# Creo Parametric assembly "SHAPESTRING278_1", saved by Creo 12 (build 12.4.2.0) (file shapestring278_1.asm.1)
Units: Custom; MM, KILOGRAM, SECS

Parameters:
  PTC_WM_ITERATION = "0"
  PTC_WM_VERSION = "-.0"
  PTC_WM_LIFECYCLE_STATE = "In Work"
  PTC_WM_LIFECYCLE = "MO_CADDocument"
  PTC_WM_CREATED_BY = "Maximilian Roepper (Z0017RMS: MO)"
  PTC_WM_CREATED_ON = "18-Sep-26 11:36:42 AM"
  PTC_WM_MODIFIED_BY = "Maximilian Roepper (Z0017RMS: MO)"
  PTC_WM_MODIFIED_ON = "18-Sep-26 11:36:46 AM"
  PDMLINKNUMBER = "PDM000071455016"
  PTC_WM_NUMBER = "PDM000071455016"

Other parameters: WEIGHT, WEIGHT_FACTOR, WEIGHT_ADD, MC_ERRORS, SUPPLIER

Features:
  1. coordinate system
  2. imported feature
  3. component "SHAPESTRING065_1"
  4. component "SHAPESTRING275_1"
  5. component "SHAPESTRING276_1"
  6. component "SHAPESTRING277_1"

Other named items: DRW_VIEW_ORG, ROUGH-GROB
